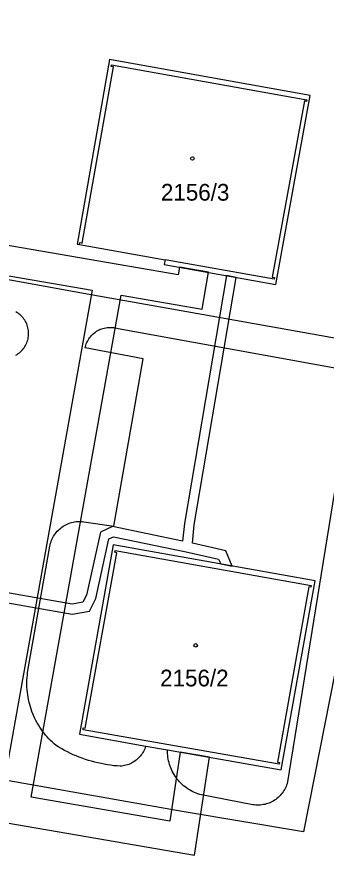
# Model space of a CAD drawing. Extents: x -756746 to -753363, y -1166406 to -1161727.
# Drawn here: x -756363.9 to -756332.4, y -1164610.7 to -1164525.4 of the extents above; entities that cross this region are included whole.
import ezdxf

# ---------------------------------------------------------------- set-up
doc = ezdxf.new("R2010")
doc.units = 0
for name, color, linetype in [('Hranice parcel', 7, 'Continuous'), ('Parcelní čísla', 7, 'Continuous'), ('Vnitřní kresba', 7, 'Continuous'), ('Věcná břemena k části', 7, 'Continuous'), ('Značky budov', 7, 'Continuous')]:
    doc.layers.add(name, color=color, linetype=linetype)

msp = doc.modelspace()

# ---------------------------------------------------------------- linework, layer by layer
at = {"layer": 'Hranice parcel'}
for points in [[(-756357.73, -1164548.53), (-756357.49, -1164548.57), (-756348.77, -1164550.13), (-756348.9, -1164550.6), (-756337.55, -1164552.64), (-756334.06, -1164533.41), (-756354.43, -1164529.78), (-756357.73, -1164548.53)], [(-756357.5, -1164598.38), (-756350.76, -1164599.59), (-756348.54, -1164599.97), (-756337, -1164602.02), (-756333.56, -1164582.78), (-756354.06, -1164579.13), (-756357.5, -1164598.38)]]:
    msp.add_lwpolyline(points, dxfattribs=at)
at = {"layer": 'Vnitřní kresba'}
for p, q in [((-756357.23, -1164548.43), (-756354.04, -1164530.52)), ((-756354.26, -1164530.48), (-756354.22, -1164530.32)), ((-756354.04, -1164530.52), (-756354.26, -1164530.48)), ((-756354.22, -1164530.32), (-756334.4, -1164533.86)), ((-756334.65, -1164533.98), (-756337.91, -1164551.89)), ((-756334.43, -1164534.03), (-756334.65, -1164533.98)), ((-756334.4, -1164533.86), (-756334.43, -1164534.03)), ((-756357.49, -1164548.57), (-756357.45, -1164548.39)), ((-756357.45, -1164548.39), (-756357.23, -1164548.43)), ((-756337.72, -1164552.1), (-756348.77, -1164550.13)), ((-756369.6, -1164551.26), (-756357.07, -1164553.53)), ((-756337.91, -1164551.89), (-756337.7, -1164551.93)), ((-756337.7, -1164551.93), (-756337.72, -1164552.1)), ((-756357.07, -1164553.53), (-756346.58, -1164555.38)), ((-756346.58, -1164555.38), (-756301.16, -1164563.58)), ((-756353.57, -1164557.13), (-756330.99, -1164561.23)), ((-756351.01, -1164560.2), (-756356.92, -1164559.1)), ((-756354.01, -1164577.23), (-756351.01, -1164560.2)), ((-756330.04, -1164564), (-756336.41, -1164603.42)), ((-756328.52, -1164576.64), (-756334.75, -1164608.32)), ((-756357.06, -1164576.77), (-756354.01, -1164577.23)), ((-756362.75, -1164592.1), (-756360.49, -1164579.26)), ((-756356.9, -1164597.77), (-756353.7, -1164579.92)), ((-756353.9, -1164579.88), (-756353.88, -1164579.71)), ((-756353.7, -1164579.92), (-756353.9, -1164579.88)), ((-756353.88, -1164579.71), (-756333.96, -1164583.25)), ((-756334.2, -1164583.38), (-756337.39, -1164601.24)), ((-756333.98, -1164583.42), (-756334.2, -1164583.38)), ((-756333.96, -1164583.25), (-756333.98, -1164583.42)), ((-756347.07, -1164606.25), (-756403.05, -1164596.27)), ((-756357.12, -1164597.93), (-756357.11, -1164597.73)), ((-756337.2, -1164601.44), (-756357.12, -1164597.93)), ((-756357.11, -1164597.73), (-756356.9, -1164597.77)), ((-756337.39, -1164601.24), (-756337.17, -1164601.27)), ((-756337.17, -1164601.27), (-756337.2, -1164601.44)), ((-756339.89, -1164605.55), (-756345.28, -1164604.51)), ((-756334.75, -1164608.32), (-756347.07, -1164606.25))]:
    msp.add_line(p, q, dxfattribs=at)
for points in [[(-756363.935, -1164559.835), (-756363.814, -1164559.761), (-756363.698, -1164559.681), (-756363.586, -1164559.595), (-756363.479, -1164559.503), (-756363.378, -1164559.404), (-756363.282, -1164559.301), (-756363.192, -1164559.192), (-756363.108, -1164559.078), (-756363.031, -1164558.96), (-756362.96, -1164558.838), (-756362.896, -1164558.712), (-756362.84, -1164558.582), (-756362.79, -1164558.45), (-756362.748, -1164558.315), (-756362.714, -1164558.178), (-756362.687, -1164558.04), (-756362.669, -1164557.9), (-756362.657, -1164557.759), (-756362.654, -1164557.618), (-756362.659, -1164557.477), (-756362.671, -1164557.336), (-756362.691, -1164557.196), (-756362.719, -1164557.058), (-756362.755, -1164556.921), (-756362.798, -1164556.787), (-756362.849, -1164556.655), (-756362.907, -1164556.526), (-756362.971, -1164556.401), (-756363.043, -1164556.279), (-756363.122, -1164556.162), (-756363.207, -1164556.049), (-756363.297, -1164555.941), (-756363.394, -1164555.838), (-756363.497, -1164555.741), (-756363.604, -1164555.649), (-756363.717, -1164555.564), (-756363.834, -1164555.485), (-756363.955, -1164555.413)], [(-756356.92, -1164559.1), (-756356.888, -1164558.962), (-756356.849, -1164558.826), (-756356.803, -1164558.692), (-756356.75, -1164558.561), (-756356.689, -1164558.434), (-756356.622, -1164558.309), (-756356.548, -1164558.189), (-756356.467, -1164558.072), (-756356.381, -1164557.961), (-756356.288, -1164557.854), (-756356.19, -1164557.752), (-756356.086, -1164557.655), (-756355.978, -1164557.565), (-756355.864, -1164557.48), (-756355.746, -1164557.402), (-756355.624, -1164557.331), (-756355.499, -1164557.266), (-756355.37, -1164557.207), (-756355.238, -1164557.156), (-756355.103, -1164557.113), (-756354.966, -1164557.076), (-756354.828, -1164557.047), (-756354.688, -1164557.026), (-756354.547, -1164557.012), (-756354.406, -1164557.006), (-756354.265, -1164557.008), (-756354.123, -1164557.017), (-756353.983, -1164557.034), (-756353.844, -1164557.059), (-756353.706, -1164557.091), (-756353.57, -1164557.13)], [(-756360.49, -1164579.26), (-756360.458, -1164579.107), (-756360.418, -1164578.957), (-756360.371, -1164578.808), (-756360.316, -1164578.662), (-756360.254, -1164578.519), (-756360.185, -1164578.379), (-756360.109, -1164578.243), (-756360.025, -1164578.112), (-756359.936, -1164577.984), (-756359.84, -1164577.861), (-756359.738, -1164577.743), (-756359.63, -1164577.631), (-756359.516, -1164577.524), (-756359.397, -1164577.423), (-756359.273, -1164577.328), (-756359.145, -1164577.24), (-756359.012, -1164577.158), (-756358.875, -1164577.083), (-756358.735, -1164577.016), (-756358.591, -1164576.955), (-756358.445, -1164576.902), (-756358.296, -1164576.856), (-756358.145, -1164576.818), (-756357.992, -1164576.787), (-756357.838, -1164576.765), (-756357.682, -1164576.75), (-756357.527, -1164576.743), (-756357.371, -1164576.744), (-756357.215, -1164576.753), (-756357.06, -1164576.77)], [(-756359.86, -1164599.54), (-756360.052, -1164599.376), (-756360.238, -1164599.205), (-756360.419, -1164599.029), (-756360.595, -1164598.848), (-756360.765, -1164598.661), (-756360.929, -1164598.47), (-756361.088, -1164598.273), (-756361.24, -1164598.071), (-756361.386, -1164597.865), (-756361.525, -1164597.655), (-756361.658, -1164597.44), (-756361.785, -1164597.222), (-756361.904, -1164596.999), (-756362.017, -1164596.773), (-756362.123, -1164596.544), (-756362.221, -1164596.311), (-756362.313, -1164596.076), (-756362.397, -1164595.838), (-756362.474, -1164595.597), (-756362.543, -1164595.355), (-756362.605, -1164595.11), (-756362.659, -1164594.863), (-756362.706, -1164594.615), (-756362.745, -1164594.366), (-756362.777, -1164594.115), (-756362.8, -1164593.864), (-756362.816, -1164593.612), (-756362.825, -1164593.359), (-756362.825, -1164593.107), (-756362.818, -1164592.854), (-756362.803, -1164592.602), (-756362.78, -1164592.351), (-756362.75, -1164592.1)], [(-756353.34, -1164601.64), (-756353.669, -1164601.615), (-756353.996, -1164601.582), (-756354.323, -1164601.541), (-756354.649, -1164601.492), (-756354.974, -1164601.436), (-756355.297, -1164601.373), (-756355.619, -1164601.301), (-756355.939, -1164601.223), (-756356.257, -1164601.137), (-756356.573, -1164601.043), (-756356.886, -1164600.942), (-756357.198, -1164600.834), (-756357.506, -1164600.718), (-756357.812, -1164600.595), (-756358.115, -1164600.465), (-756358.414, -1164600.328), (-756358.711, -1164600.184), (-756359.004, -1164600.033), (-756359.293, -1164599.876), (-756359.578, -1164599.711), (-756359.86, -1164599.54)], [(-756350.76, -1164599.59), (-756350.806, -1164599.729), (-756350.859, -1164599.865), (-756350.919, -1164599.998), (-756350.985, -1164600.128), (-756351.058, -1164600.255), (-756351.137, -1164600.377), (-756351.222, -1164600.496), (-756351.313, -1164600.61), (-756351.41, -1164600.719), (-756351.512, -1164600.824), (-756351.619, -1164600.923), (-756351.731, -1164601.017), (-756351.847, -1164601.105), (-756351.968, -1164601.187), (-756352.093, -1164601.262), (-756352.221, -1164601.332), (-756352.353, -1164601.395), (-756352.488, -1164601.451), (-756352.625, -1164601.5), (-756352.765, -1164601.542), (-756352.907, -1164601.578), (-756353.05, -1164601.606), (-756353.195, -1164601.626), (-756353.34, -1164601.64)], [(-756345.28, -1164604.51), (-756345.459, -1164604.452), (-756345.635, -1164604.387), (-756345.808, -1164604.314), (-756345.978, -1164604.235), (-756346.145, -1164604.149), (-756346.308, -1164604.056), (-756346.467, -1164603.956), (-756346.622, -1164603.85), (-756346.772, -1164603.737), (-756346.918, -1164603.619), (-756347.059, -1164603.495), (-756347.195, -1164603.365), (-756347.325, -1164603.23), (-756347.449, -1164603.089), (-756347.568, -1164602.944), (-756347.681, -1164602.793), (-756347.787, -1164602.639), (-756347.887, -1164602.48), (-756347.98, -1164602.317), (-756348.067, -1164602.15), (-756348.147, -1164601.98), (-756348.219, -1164601.807), (-756348.285, -1164601.631), (-756348.343, -1164601.453), (-756348.394, -1164601.272), (-756348.438, -1164601.089), (-756348.474, -1164600.905), (-756348.502, -1164600.719), (-756348.523, -1164600.533), (-756348.537, -1164600.345), (-756348.542, -1164600.158), (-756348.54, -1164599.97)], [(-756336.41, -1164603.42), (-756336.459, -1164603.565), (-756336.516, -1164603.708), (-756336.579, -1164603.848), (-756336.65, -1164603.985), (-756336.727, -1164604.118), (-756336.81, -1164604.247), (-756336.9, -1164604.371), (-756336.996, -1164604.491), (-756337.097, -1164604.606), (-756337.205, -1164604.716), (-756337.317, -1164604.821), (-756337.435, -1164604.919), (-756337.557, -1164605.012), (-756337.684, -1164605.099), (-756337.815, -1164605.179), (-756337.95, -1164605.252), (-756338.088, -1164605.319), (-756338.23, -1164605.379), (-756338.374, -1164605.432), (-756338.521, -1164605.477), (-756338.67, -1164605.516), (-756338.82, -1164605.546), (-756338.972, -1164605.57), (-756339.125, -1164605.585), (-756339.278, -1164605.594), (-756339.432, -1164605.594), (-756339.585, -1164605.587), (-756339.738, -1164605.572), (-756339.89, -1164605.55)]]:
    msp.add_lwpolyline(points, dxfattribs=at)
at = {"layer": 'Věcná břemena k části'}
for points in [[(-756375.48, -1164506.22), (-756380.59, -1164535.04), (-756382.69, -1164534.67), (-756383.21, -1164537.62), (-756381.11, -1164537.99), (-756386.28, -1164567.14), (-756388.43, -1164566.76), (-756388.96, -1164569.71), (-756383.85, -1164570.62), (-756380.04, -1164549.11), (-756356.2, -1164553.22), (-756365.88, -1164607.22), (-756345.82, -1164610.69), (-756344.3, -1164600.72), (-756347.25, -1164600.2), (-756348.32, -1164607.21), (-756362.39, -1164604.78), (-756353.24, -1164553.73), (-756345.03, -1164555.14), (-756344.37, -1164551.41), (-756347.32, -1164550.88), (-756347.46, -1164551.68), (-756379.51, -1164546.15), (-756355.15, -1164408.82)], [(-756375.2, -1164583.19), (-756358.23, -1164586.19), (-756356.46, -1164585.86), (-756355.84, -1164584.59), (-756354.49, -1164578.52), (-756354.03, -1164578.31), (-756346.67, -1164579.83), (-756343.36, -1164580.59), (-756343.15, -1164581.07), (-756341.97, -1164581.28), (-756342.64, -1164579.73), (-756346.02, -1164578.95), (-756345.84, -1164577.09), (-756341.58, -1164551.92), (-756342.56, -1164551.74), (-756346.84, -1164576.95), (-756347.01, -1164578.74), (-756354.15, -1164577.27), (-756355.35, -1164577.82), (-756356.78, -1164584.25), (-756357.14, -1164584.96), (-756358.23, -1164585.17), (-756375.62, -1164582.1)]]:
    msp.add_lwpolyline(points, dxfattribs=at)
at = {"layer": 'Značky budov'}
for centre in [(-756346.027, -1164539.829), (-756345.687, -1164589.349)]:
    msp.add_circle(centre, 0.175, dxfattribs=at)

# ---------------------------------------------------------------- texts
at = {"layer": 'Parcelní čísla'}
for s, p in [('2156/3', (-756349.22, -1164544.12)), ('2156/2', (-756349.3, -1164593.52))]:
    msp.add_text(s, height=1.7, dxfattribs=at).set_placement(p)

doc.saveas('drawing.dxf')
